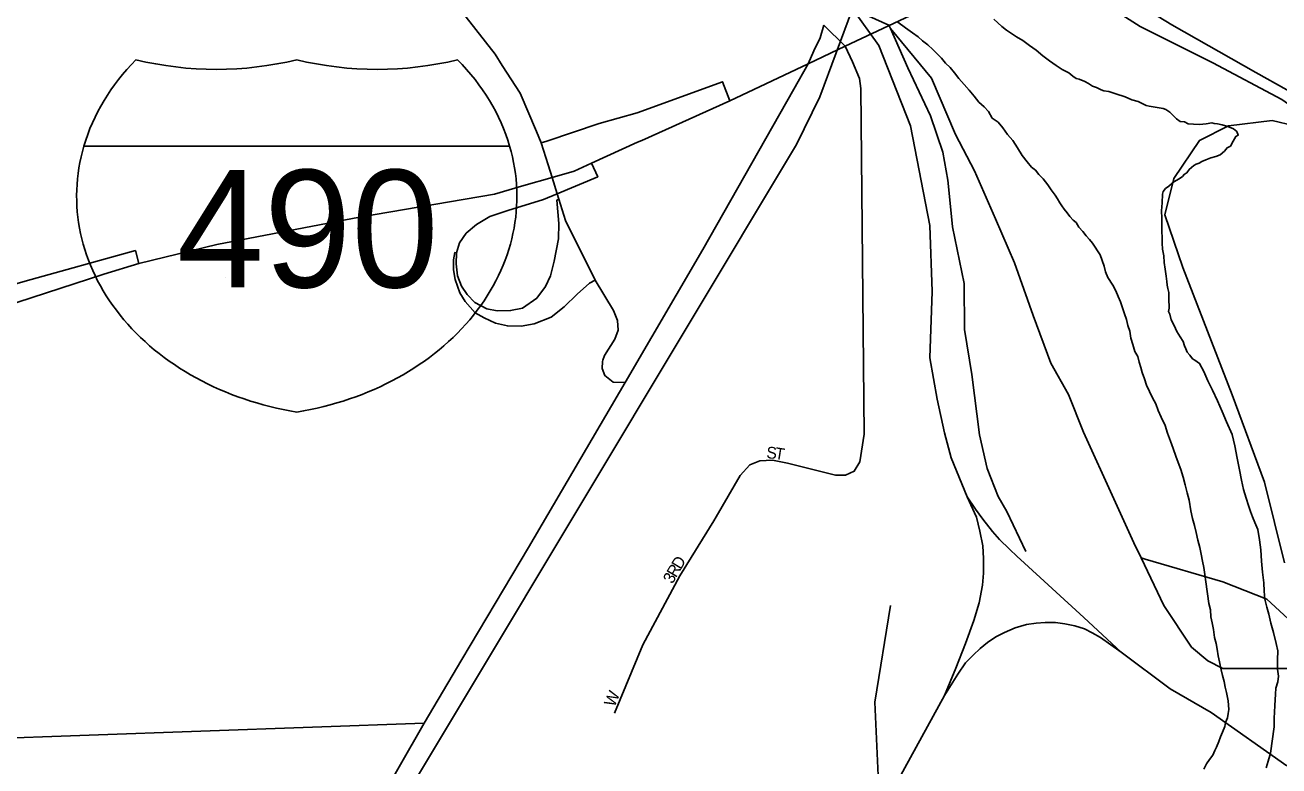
# Model space of a CAD drawing. Extents: x -561 to 1170, y 0 to 846.
# Drawn here: x 246.55 to 260.97, y 259.77 to 268.29 of the extents above; entities that cross this region are included whole.
import ezdxf

# ---------------------------------------------------------------- set-up
doc = ezdxf.new("R2010")
doc.units = 0
for name, color, linetype in [('GM_X_City_Street', 7, 'Continuous'), ('GM_X_City_Street_Text', 7, 'Continuous'), ('GM_X_Interchange_Ramps', 7, 'Continuous'), ('GM_X_Interstate_Location', 7, 'Continuous'), ('GM_X_Interstate_Route', 7, 'Continuous'), ('GM_X_Interstate_Shield', 7, 'Continuous'), ('GM_X_Major_River', 7, 'Continuous'), ('GM_X_Rail_Line', 7, 'Continuous')]:
    doc.layers.add(name, color=color, linetype=linetype)

msp = doc.modelspace()

# ---------------------------------------------------------------- linework, layer by layer
at = {"layer": 'GM_X_City_Street'}
for points in [[(250.108, 270.314), (251.953, 267.951), (252.035, 267.824)], [(260.702, 267.742), (259.733, 268.291), (259.105, 268.678)], [(255.732, 268.287), (255.691, 268.139), (255.62, 267.991), (255.552, 267.842), (255.39, 267.551), (254.343, 265.707), (253.447, 264.177)], [(254.495, 262.635), (254.77, 263.11), (254.881, 263.233), (254.996, 263.276), (255.141, 263.284), (255.317, 263.25), (255.868, 263.113), (255.983, 263.113), (256.082, 263.16), (256.146, 263.267), (256.195, 263.585), (256.158, 267.557), (256.142, 267.675), (256.063, 267.865), (255.977, 268.043), (255.732, 268.287)], [(252.035, 267.824), (252.241, 267.503), (252.428, 267.064)], [(261.183, 262.952), (261.181, 262.995), (261.18, 263.094), (261.174, 263.747), (261.317, 264.241), (261.496, 264.872), (261.659, 265.524), (261.848, 266.131), (261.867, 266.364), (261.818, 266.649), (261.708, 266.922), (261.549, 267.158), (261.369, 267.339), (261.057, 267.541), (260.702, 267.742)], [(252.428, 267.064), (252.484, 266.932), (252.562, 266.681), (252.608, 266.535), (252.667, 266.348), (252.687, 266.284), (252.764, 266.04), (253.104, 265.356), (253.316, 265.004), (253.359, 264.889), (253.367, 264.781), (253.331, 264.677), (253.212, 264.487), (253.193, 264.435)], [(253.193, 264.435), (253.187, 264.419), (253.185, 264.338), (253.216, 264.258), (253.311, 264.18), (253.447, 264.177)], [(253.447, 264.177), (252.336, 262.282), (251.572, 260.994)], [(253.326, 260.377), (253.65, 261.163), (254.076, 261.954), (254.467, 262.586), (254.495, 262.635)], [(251.572, 260.994), (251.137, 260.26)], [(245.996, 260.076), (251.137, 260.26)], [(251.137, 260.26), (251.137, 260.26), (250.576, 259.284), (250.189, 258.616), (249.901, 258.213), (248.954, 257.374), (248.661, 257.122)]]:
    msp.add_lwpolyline(points, dxfattribs=at)
at = {"layer": 'GM_X_Interchange_Ramps'}
for points in [[(254.654, 267.415), (254.567, 267.635), (253.587, 267.28), (253.151, 267.154), (252.548, 266.953), (252.484, 266.932)], [(252.687, 266.284), (252.663, 266.275), (252.685, 266.007), (252.681, 265.831), (252.633, 265.574), (252.589, 265.405), (252.531, 265.28), (252.432, 265.148), (252.267, 265.034), (252.131, 265.005), (251.977, 265.001), (251.856, 265.023), (251.72, 265.097), (251.632, 265.188), (251.566, 265.287), (251.522, 265.405), (251.507, 265.541), (251.511, 265.669), (251.544, 265.783), (251.621, 265.893), (251.738, 265.996), (251.892, 266.088), (252.098, 266.157), (252.509, 266.282), (252.667, 266.348), (253.133, 266.543), (253.063, 266.699)], [(247.858, 265.546), (247.817, 265.695), (246.548, 265.342), (245.539, 265.05), (244.955, 264.935), (244.496, 264.862), (244.117, 264.788), (244.062, 264.771), (243.742, 264.674), (243.393, 264.531), (243.089, 264.343), (242.888, 264.173), (242.862, 264.139), (242.796, 264.053), (242.783, 264.036), (242.65, 263.863), (242.49, 263.592), (242.393, 263.326), (242.351, 263.082), (242.32, 262.79), (242.317, 262.469), (242.348, 262.215), (242.405, 261.658), (242.371, 261.651)], [(253.104, 265.356), (253.037, 265.321), (252.898, 265.192), (252.747, 265.049), (252.597, 264.931), (252.402, 264.851), (252.252, 264.825), (252.094, 264.829), (251.958, 264.862), (251.826, 264.92), (251.723, 264.979), (251.61, 265.108), (251.547, 265.21), (251.492, 265.361), (251.475, 265.473), (251.475, 265.588), (251.489, 265.672), (251.511, 265.669)]]:
    msp.add_lwpolyline(points, dxfattribs=at)
at = {"layer": 'GM_X_Interstate_Route'}
for points in [[(253.592, 266.94), (253.639, 266.962), (254.654, 267.415), (255.552, 267.842), (255.977, 268.043), (257.85, 268.928), (258.493, 269.116), (259.023, 269.271), (259.957, 269.51), (260.676, 269.667), (260.999, 269.711), (261.166, 269.734), (261.737, 269.813)], [(252.285, 266.441), (252.608, 266.535), (252.864, 266.609), (253.063, 266.699), (253.592, 266.94)], [(243.997, 264.342), (244.066, 264.357), (244.214, 264.387), (244.703, 264.513), (246.453, 265.099), (247.455, 265.423), (247.858, 265.546), (248.754, 265.763), (250.392, 266.077), (251.947, 266.344), (252.285, 266.441)]]:
    msp.add_lwpolyline(points, dxfattribs=at)
at = {"layer": 'GM_X_Interstate_Shield'}
msp.add_line((252.12, 266.896), (247.225, 266.896), dxfattribs=at)
msp.add_line((252.12, 266.896), (247.225, 266.896), dxfattribs=at)
for centre, start_param, end_param in [((250.305, 266.318), 2.47259, 2.911027), ((248.748, 270.309), 4.415841, 5.008937), ((250.597, 270.309), 4.415841, 5.008937), ((249.04, 266.318), 0.230566, 0.669003), ((250.305, 266.318), 2.911027, 4.511031), ((249.04, 266.318), 4.913747, 6.513751)]:
    msp.add_ellipse(centre, major_axis=(3.164, 0), ratio=0.8, start_param=start_param, end_param=end_param, dxfattribs=at)
at = {"layer": 'GM_X_Major_River'}
for points in [[(256.584, 268.321), (256.671, 268.257), (256.753, 268.199), (256.819, 268.151), (256.868, 268.108), (256.928, 268.06), (256.988, 268.007), (257.038, 267.958), (257.087, 267.905), (257.131, 267.851), (257.186, 267.798), (257.236, 267.739), (257.285, 267.674), (257.346, 267.605), (257.406, 267.54), (257.461, 267.47), (257.516, 267.401), (257.577, 267.347), (257.626, 267.294), (257.67, 267.218), (257.736, 267.17), (257.791, 267.106), (257.846, 267.031), (257.907, 266.961), (257.962, 266.875), (258.012, 266.789), (258.072, 266.714), (258.122, 266.655), (258.166, 266.618), (258.204, 266.569), (258.254, 266.521), (258.309, 266.451), (258.348, 266.392), (258.392, 266.333), (258.419, 266.29), (258.447, 266.242), (258.469, 266.21), (258.497, 266.172), (258.53, 266.129), (258.563, 266.086), (258.601, 266.043), (258.634, 266.017), (258.667, 265.963), (258.711, 265.914), (258.75, 265.866), (258.788, 265.823), (258.821, 265.78), (258.91, 265.646), (258.932, 265.581), (258.955, 265.517), (258.972, 265.452), (259, 265.387), (259.055, 265.296), (259.089, 265.231), (259.117, 265.166), (259.145, 265.107), (259.167, 265.037), (259.19, 264.967)], [(259.19, 264.967), (259.167, 265.037), (259.145, 265.107), (259.117, 265.166), (259.089, 265.231), (259.055, 265.296), (259, 265.387), (258.972, 265.452), (258.955, 265.517), (258.932, 265.581), (258.91, 265.646), (258.821, 265.78), (258.788, 265.823), (258.75, 265.866), (258.711, 265.914), (258.667, 265.963), (258.634, 266.017), (258.601, 266.043), (258.563, 266.086), (258.53, 266.129), (258.497, 266.172), (258.469, 266.21), (258.447, 266.242), (258.419, 266.29), (258.392, 266.333), (258.348, 266.392), (258.309, 266.451), (258.254, 266.521), (258.204, 266.569), (258.166, 266.618), (258.122, 266.655), (258.072, 266.714), (258.012, 266.789), (257.962, 266.875), (257.907, 266.961), (257.846, 267.031), (257.791, 267.106), (257.736, 267.17), (257.67, 267.218), (257.626, 267.294), (257.577, 267.347), (257.516, 267.401), (257.461, 267.47), (257.406, 267.54), (257.346, 267.605), (257.285, 267.674), (257.236, 267.739), (257.186, 267.798), (257.131, 267.851), (257.087, 267.905), (257.038, 267.958), (256.988, 268.007), (256.928, 268.06), (256.868, 268.108), (256.819, 268.151), (256.753, 268.199), (256.671, 268.257), (256.584, 268.321)], [(258.633, 267.674), (258.595, 267.701), (258.551, 267.738), (258.475, 267.775), (258.404, 267.823), (258.327, 267.876), (258.251, 267.935), (258.174, 267.999), (258.097, 268.052), (258.021, 268.111), (257.95, 268.154), (257.89, 268.191), (257.835, 268.228), (257.781, 268.271), (257.687, 268.356)], [(257.687, 268.356), (257.781, 268.271), (257.835, 268.228), (257.89, 268.191), (257.95, 268.154), (258.021, 268.111), (258.097, 268.052), (258.174, 267.999), (258.251, 267.935), (258.327, 267.876), (258.404, 267.823), (258.475, 267.775), (258.551, 267.738), (258.595, 267.701), (258.633, 267.674)], [(260.485, 263.308), (260.461, 263.449), (260.427, 263.579), (260.365, 263.724), (260.315, 263.843), (260.259, 263.967), (260.203, 264.091), (260.148, 264.198), (260.103, 264.306), (260.053, 264.398), (259.998, 264.435), (259.971, 264.451), (259.943, 264.494), (259.91, 264.526), (259.894, 264.564), (259.882, 264.601), (259.865, 264.65), (259.832, 264.704), (259.793, 264.763), (259.76, 264.833), (259.727, 264.897), (259.71, 264.962), (259.698, 264.995), (259.703, 265.033), (259.703, 265.065), (259.702, 265.114), (259.701, 265.163), (259.701, 265.211), (259.689, 265.26), (259.683, 265.298), (259.677, 265.341), (259.671, 265.401), (259.659, 265.482), (259.647, 265.557), (259.641, 265.633), (259.629, 265.709), (259.623, 265.779), (259.622, 265.844), (259.621, 265.915), (259.62, 265.985), (259.619, 266.066), (259.617, 266.153), (259.622, 266.245), (259.626, 266.343), (259.636, 266.375), (259.663, 266.408), (259.7, 266.436), (259.759, 266.485), (259.818, 266.518), (259.856, 266.546), (259.882, 266.573), (259.909, 266.59), (259.936, 266.628), (259.989, 266.672), (260.016, 266.689), (260.048, 266.7), (260.081, 266.717), (260.124, 266.739), (260.183, 266.761), (260.242, 266.778), (260.291, 266.795), (260.339, 266.839), (260.371, 266.877), (260.408, 266.894), (260.44, 266.954), (260.472, 267.008), (260.499, 267.02), (260.482, 267.063), (260.444, 267.095), (260.378, 267.121), (260.313, 267.142), (260.259, 267.152), (260.221, 267.157), (260.194, 267.162), (260.129, 267.151), (260.053, 267.144), (259.983, 267.149), (259.923, 267.153), (259.879, 267.175), (259.831, 267.179), (259.787, 267.211), (259.749, 267.249), (259.71, 267.286), (259.666, 267.318), (259.634, 267.329), (259.476, 267.354), (259.438, 267.364), (259.395, 267.385), (259.346, 267.407), (259.275, 267.427), (259.199, 267.464), (259.09, 267.496), (259.009, 267.522), (258.954, 267.532), (258.922, 267.542), (258.867, 267.569), (258.824, 267.584), (258.775, 267.616), (258.736, 267.638), (258.671, 267.664), (258.633, 267.674)], [(258.633, 267.674), (258.671, 267.664), (258.736, 267.638), (258.775, 267.616), (258.824, 267.584), (258.867, 267.569), (258.922, 267.542), (258.954, 267.532), (259.009, 267.522), (259.09, 267.496), (259.199, 267.464), (259.275, 267.427), (259.346, 267.407), (259.395, 267.385), (259.438, 267.364), (259.476, 267.354), (259.634, 267.329), (259.666, 267.318), (259.71, 267.286), (259.749, 267.249), (259.787, 267.211), (259.831, 267.179), (259.879, 267.175), (259.923, 267.153), (259.983, 267.149), (260.053, 267.144), (260.129, 267.151), (260.194, 267.162), (260.221, 267.157), (260.259, 267.152), (260.313, 267.142), (260.378, 267.121), (260.444, 267.095), (260.482, 267.063), (260.499, 267.02), (260.472, 267.008), (260.44, 266.954), (260.408, 266.894), (260.371, 266.877), (260.339, 266.839), (260.291, 266.795), (260.242, 266.778), (260.183, 266.761), (260.124, 266.739), (260.081, 266.717), (260.048, 266.7), (260.016, 266.689), (259.989, 266.672), (259.936, 266.628), (259.909, 266.59), (259.882, 266.573), (259.856, 266.546), (259.818, 266.518), (259.759, 266.485), (259.7, 266.436), (259.663, 266.408), (259.636, 266.375), (259.626, 266.343), (259.622, 266.245), (259.617, 266.153), (259.619, 266.066), (259.62, 265.985), (259.621, 265.915), (259.622, 265.844), (259.623, 265.779), (259.629, 265.709), (259.641, 265.633), (259.647, 265.557), (259.659, 265.482), (259.671, 265.401), (259.677, 265.341), (259.683, 265.298), (259.689, 265.26), (259.701, 265.211), (259.701, 265.163), (259.702, 265.114), (259.703, 265.065), (259.703, 265.033), (259.698, 264.995), (259.71, 264.962), (259.727, 264.897), (259.76, 264.833), (259.793, 264.763), (259.832, 264.704), (259.865, 264.65), (259.882, 264.601), (259.894, 264.564), (259.91, 264.526), (259.943, 264.494), (259.971, 264.451), (259.998, 264.435), (260.053, 264.398), (260.103, 264.306), (260.148, 264.198), (260.203, 264.091), (260.259, 263.967), (260.315, 263.843), (260.365, 263.724), (260.427, 263.579), (260.461, 263.449), (260.485, 263.308)], [(259.19, 264.967), (259.212, 264.902), (259.23, 264.832), (259.252, 264.767), (259.264, 264.686), (259.287, 264.616), (259.309, 264.535), (259.343, 264.476), (259.36, 264.411), (259.377, 264.351), (259.394, 264.292), (259.422, 264.222), (259.445, 264.146), (259.478, 264.076), (259.512, 264.001), (259.55, 263.931), (259.579, 263.855), (259.612, 263.78), (259.657, 263.683), (259.685, 263.597), (259.719, 263.505), (259.752, 263.419), (259.781, 263.332), (259.809, 263.257), (259.837, 263.176), (259.865, 263.09), (259.888, 263.003), (259.911, 262.911), (259.934, 262.825), (259.952, 262.701), (259.974, 262.614), (259.997, 262.533), (260.015, 262.452), (260.032, 262.366), (260.055, 262.279), (260.072, 262.204), (260.089, 262.123), (260.101, 262.052), (260.113, 261.971), (260.125, 261.885), (260.161, 261.636), (260.178, 261.566), (260.185, 261.485), (260.197, 261.414), (260.214, 261.339), (260.226, 261.247), (260.243, 261.176), (260.255, 261.112), (260.267, 261.036), (260.284, 260.966), (260.301, 260.874), (260.319, 260.809), (260.336, 260.739), (260.347, 260.674), (260.365, 260.614), (260.376, 260.555), (260.382, 260.517), (260.388, 260.468), (260.389, 260.42), (260.384, 260.371), (260.374, 260.322), (260.353, 260.268), (260.343, 260.224), (260.317, 260.159), (260.296, 260.104), (260.275, 260.05), (260.249, 259.985), (260.228, 259.946), (260.207, 259.892), (260.169, 259.843), (260.132, 259.794), (260.101, 259.734)], [(260.101, 259.734), (260.132, 259.794), (260.169, 259.843), (260.207, 259.892), (260.228, 259.946), (260.249, 259.985), (260.275, 260.05), (260.296, 260.104), (260.317, 260.159), (260.343, 260.224), (260.353, 260.268), (260.374, 260.322), (260.384, 260.371), (260.389, 260.42), (260.388, 260.468), (260.382, 260.517), (260.376, 260.555), (260.365, 260.614), (260.347, 260.674), (260.336, 260.739), (260.319, 260.809), (260.301, 260.874), (260.284, 260.966), (260.267, 261.036), (260.255, 261.112), (260.243, 261.176), (260.226, 261.247), (260.214, 261.339), (260.197, 261.414), (260.185, 261.485), (260.178, 261.566), (260.161, 261.636), (260.125, 261.885), (260.113, 261.971), (260.101, 262.052), (260.089, 262.123), (260.072, 262.204), (260.055, 262.279), (260.032, 262.366), (260.015, 262.452), (259.997, 262.533), (259.974, 262.614), (259.952, 262.701), (259.934, 262.825), (259.911, 262.911), (259.888, 263.003), (259.865, 263.09), (259.837, 263.176), (259.809, 263.257), (259.781, 263.332), (259.752, 263.419), (259.719, 263.505), (259.685, 263.597), (259.657, 263.683), (259.612, 263.78), (259.579, 263.855), (259.55, 263.931), (259.512, 264.001), (259.478, 264.076), (259.445, 264.146), (259.422, 264.222), (259.394, 264.292), (259.377, 264.351), (259.36, 264.411), (259.343, 264.476), (259.309, 264.535), (259.287, 264.616), (259.264, 264.686), (259.252, 264.767), (259.23, 264.832), (259.212, 264.902), (259.19, 264.967)], [(260.87, 259.917), (260.911, 260.22), (260.91, 260.318), (260.914, 260.388), (260.919, 260.464), (260.923, 260.529), (260.928, 260.594), (260.932, 260.665), (260.953, 260.735), (260.963, 260.8), (260.951, 260.882), (260.949, 260.99), (260.953, 261.093), (260.936, 261.179), (260.902, 261.304), (260.873, 261.412), (260.85, 261.514), (260.827, 261.595), (260.804, 261.687), (260.798, 261.779), (260.791, 261.876), (260.779, 261.996), (260.766, 262.125), (260.759, 262.255), (260.741, 262.369), (260.723, 262.488), (260.69, 262.569), (260.662, 262.633), (260.639, 262.693), (260.617, 262.763), (260.588, 262.849), (260.56, 262.946), (260.537, 263.054), (260.513, 263.173), (260.485, 263.308)], [(260.485, 263.308), (260.513, 263.173), (260.537, 263.054), (260.56, 262.946), (260.588, 262.849), (260.617, 262.763), (260.639, 262.693), (260.662, 262.633), (260.69, 262.569), (260.723, 262.488), (260.741, 262.369), (260.759, 262.255), (260.766, 262.125), (260.779, 261.996), (260.791, 261.876), (260.798, 261.779), (260.804, 261.687), (260.827, 261.595), (260.85, 261.514), (260.873, 261.412), (260.902, 261.304), (260.936, 261.179), (260.953, 261.093), (260.949, 260.99), (260.951, 260.882), (260.963, 260.8), (260.953, 260.735), (260.932, 260.665), (260.928, 260.594), (260.923, 260.529), (260.919, 260.464), (260.914, 260.388), (260.91, 260.318), (260.911, 260.22), (260.87, 259.917)], [(260.82, 259.748), (260.841, 259.824), (260.862, 259.889), (260.87, 259.917)], [(260.87, 259.917), (260.862, 259.889), (260.841, 259.824), (260.82, 259.748)]]:
    msp.add_lwpolyline(points, dxfattribs=at)
at = {"layer": 'GM_X_Rail_Line'}
for points in [[(257.233, 271.462), (257.247, 270.812), (257.435, 270.047), (257.955, 269.382), (258.72, 268.689), (259.37, 268.27), (260.207, 267.852), (261.001, 267.433), (261.362, 267.173), (261.528, 266.879)], [(250.424, 258.587), (255.419, 266.913), (255.688, 267.462), (256.064, 268.473)], [(256.064, 268.473), (256.367, 268.054), (256.728, 267.129), (256.953, 265.984), (256.978, 265.223), (256.953, 264.462), (257.038, 263.988), (257.122, 263.599), (257.198, 263.311), (257.382, 262.862)], [(256.498, 268.248), (256.482, 268.285), (256.064, 268.473)], [(257.164, 266.468), (257.16, 266.504), (257.103, 266.826), (256.959, 267.245), (256.699, 267.794), (256.498, 268.248)], [(256.498, 268.248), (256.973, 267.678), (257.247, 267.028), (257.464, 266.61), (257.709, 266.061), (257.926, 265.555), (258.142, 264.949), (258.345, 264.4), (258.547, 264.039), (258.72, 263.606)], [(261.528, 266.879), (261.145, 267.129), (260.887, 267.192), (260.386, 267.13), (260.052, 266.962), (259.759, 266.524), (259.654, 266.106), (259.863, 265.5), (260.427, 264.036), (260.802, 263.033), (261.03, 262.104)], [(258.057, 262.235), (257.839, 262.696), (257.738, 262.869), (257.612, 263.189), (257.522, 263.577), (257.435, 264.27), (257.351, 264.788), (257.347, 265.318), (257.214, 265.968), (257.164, 266.468)], [(258.72, 263.606), (259.066, 262.84), (259.297, 262.335), (259.381, 262.161)], [(257.382, 262.862), (257.487, 262.63), (257.527, 262.469), (257.561, 262.3), (257.571, 262.156), (257.568, 261.987), (257.558, 261.847), (257.52, 261.644), (257.458, 261.442), (257.361, 261.178), (257.251, 260.894), (257.121, 260.581)], [(257.382, 262.862), (257.477, 262.721), (257.561, 262.606), (257.671, 262.463), (257.753, 262.373), (257.868, 262.263), (257.958, 262.179), (257.996, 262.143)], [(257.996, 262.143), (258.721, 261.475), (259.151, 261.079)], [(261.122, 261.414), (260.828, 261.685), (260.322, 261.887), (259.427, 262.147), (259.381, 262.161)], [(259.381, 262.161), (259.644, 261.613), (259.961, 261.136), (260.149, 260.977), (260.322, 260.891), (260.712, 260.891), (261.16, 260.891)], [(256.319, 260.503), (256.498, 261.614)], [(257.121, 260.581), (257.275, 260.824), (257.364, 260.955), (257.449, 261.044), (257.529, 261.12), (257.615, 261.188), (257.71, 261.252), (257.811, 261.305), (257.935, 261.356), (258.063, 261.396), (258.175, 261.411), (258.28, 261.419), (258.396, 261.417), (258.503, 261.405), (258.619, 261.382), (258.73, 261.344), (258.819, 261.301), (258.914, 261.246), (259.151, 261.079)], [(259.151, 261.079), (259.714, 260.655), (260.188, 260.382), (261.056, 259.77)], [(257.121, 260.581), (256.186, 258.875)], [(249.965, 244.988), (250.527, 246.012), (252.857, 250.943), (253.84, 252.977), (254.042, 253.54), (254.461, 254.984), (254.779, 255.793), (255.111, 256.717), (255.414, 257.367), (255.731, 258.133), (256.035, 258.782), (256.367, 259.49), (256.319, 260.503)]]:
    msp.add_lwpolyline(points, dxfattribs=at)

# ---------------------------------------------------------------- texts
at = {"layer": 'GM_X_City_Street_Text'}
for s, rotation, p in [('S', 356.7474, (255.07, 263.306)), ('T', 350.8342, (255.162, 263.301)), ('D', 58.7176, (254.087, 262.019)), ('3', 60.7664, (253.993, 261.855)), ('R', 59.5985, (254.033, 261.927)), ('W', 67.3711, (253.326, 260.439))]:
    msp.add_text(s, height=0.135, rotation=rotation, dxfattribs=at).set_placement(p)
at = {"layer": 'GM_X_Interstate_Location'}
for s in ['-', '.', ',']:
    msp.add_text(s, height=0.0027, dxfattribs=at).set_placement((249.672, 265.946))
msp.add_text('490', height=0.0027, rotation=0, dxfattribs=at).set_placement((248.847, 265.387))
at = {"layer": 'GM_X_Interstate_Shield'}
msp.add_text('490', height=1.35, dxfattribs=at).set_placement((248.292, 265.272))

doc.saveas('drawing.dxf')
